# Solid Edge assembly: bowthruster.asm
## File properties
Author: Mac
Template: Normal.asm
Last saved by: Mac
Revision: 2
Application: Solid Edge
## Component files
jalg.par
kruvi.par
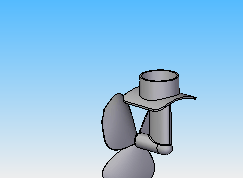
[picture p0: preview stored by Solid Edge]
